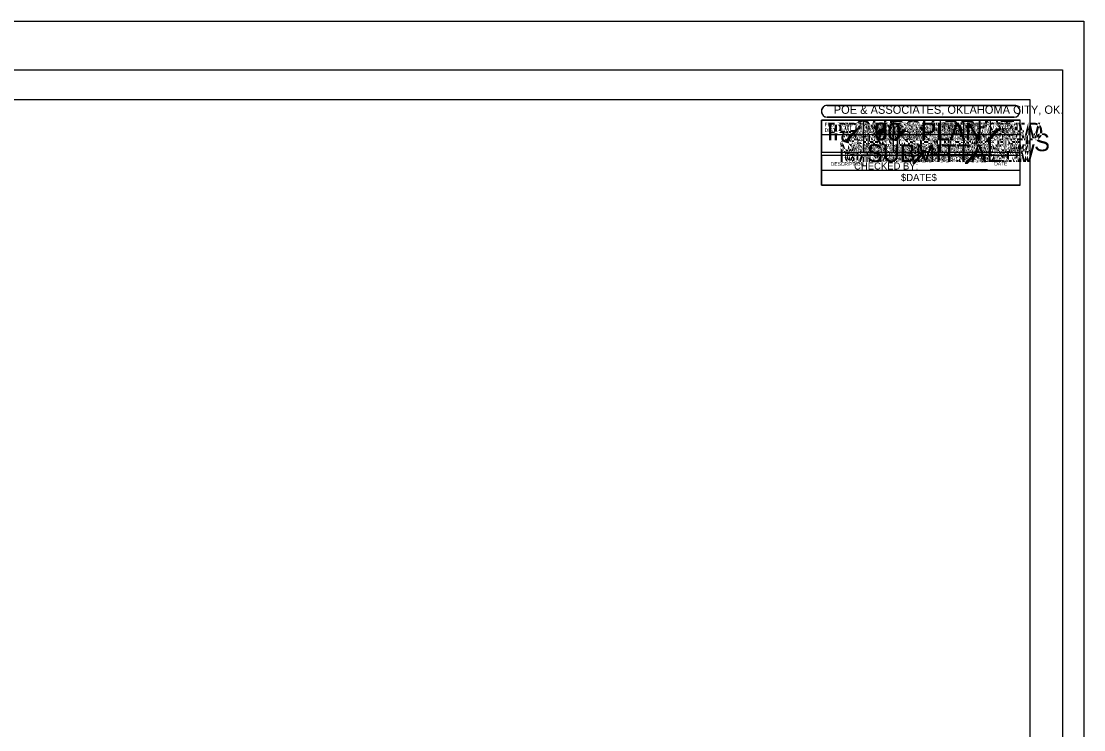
# Model space of a CAD drawing. Extents: x -434 to 1366, y -662 to 538.
# Drawn here: x 466 to 1366, y -62 to 538 of the extents above; entities that cross this region are included whole.
import ezdxf

# ---------------------------------------------------------------- set-up
doc = ezdxf.new("R2010")
doc.units = 0
for name, color, linetype in [('SHT_Date_Stamp', 7, 'Continuous'), ('SHT_Plot_Shape_Full', 7, 'Continuous'), ('SHT_Plot_Shape_Half', 7, 'Continuous'), ('SHT_Sheet_Border', 7, 'Continuous'), ('SHT_Stamp_30_Submit', 7, 'Continuous'), ('SHT_Stamp_60_Submit', 7, 'Continuous'), ('SHT_Stamp_70_Submit', 7, 'Continuous'), ('SHT_Stamp_90_Submit', 7, 'Continuous'), ('SHT_Stamp_Check_Print', 7, 'Continuous'), ('SHT_Stamp_Est_Inf', 7, 'Continuous'), ('SHT_Stamp_FFR', 7, 'Continuous'), ('SHT_Stamp_Info_Material', 7, 'Continuous'), ('SHT_Stamp_No_Const', 7, 'Continuous'), ('SHT_Stamp_No_Design', 7, 'Continuous'), ('SHT_Stamp_Plan_Hand', 7, 'Continuous'), ('SHT_Stamp_Pre_Plan', 7, 'Continuous'), ('SHT_Stamp_Prop_RW', 7, 'Continuous'), ('SHT_Stamp_Ret_Sub', 7, 'Continuous'), ('SHT_Stamp_Rev_Block', 7, 'Continuous'), ('SHT_Stamp_Rev_Prop_RW', 7, 'Continuous'), ('SHT_Stamp_Rev_Sheet', 7, 'Continuous'), ('SHT_Stamp_RW_Utilities_Meeting', 7, 'Continuous'), ('SHT_Stamp_RW_Utilities_Review', 7, 'Continuous'), ('SHT_Stamp_Send_Comments', 7, 'Continuous')]:
    doc.layers.add(name, color=color, linetype=linetype)

msp = doc.modelspace()

# ---------------------------------------------------------------- linework, layer by layer
at = {"layer": 'SHT_Plot_Shape_Full'}
msp.add_lwpolyline([(-433.98, 538.27), (1366.02, 538.27), (1366.02, -661.73), (-433.98, -661.73)], close=True, dxfattribs=at)
at = {"layer": 'SHT_Plot_Shape_Half'}
msp.add_lwpolyline([(-352.1, 497.02), (1347.9, 497.02), (1347.9, -602.98), (-352.1, -602.98)], close=True, dxfattribs=at)
at = {"layer": 'SHT_Sheet_Border'}
msp.add_lwpolyline([(1320.4, -577.98), (-254.6, -577.98), (-254.6, 472.02), (1320.4, 472.02)], close=True, dxfattribs=at)
at = {"layer": 'SHT_Stamp_30_Submit'}
for p, q in [((1148.77, 467.02), (1307.06, 467.02)), ((1143.77, 454.52), (1312.06, 454.52)), ((1143.77, 399.57), (1143.77, 454.52)), ((1148.77, 457.02), (1307.06, 457.02)), ((1312.06, 399.57), (1312.06, 454.52)), ((1205.93, 437.61), (1213.71, 446.24)), ((1206.82, 437.61), (1214.6, 446.24)), ((1207.07, 437.61), (1214.85, 446.24)), ((1207.46, 437.61), (1215.24, 446.24)), ((1213.71, 446.24), (1215.24, 446.24)), ((1205.93, 437.61), (1207.46, 437.61)), ((1143.77, 399.57), (1312.06, 399.57))]:
    msp.add_line(p, q, dxfattribs=at)
for centre, start, end in [((1148.78, 462.04), 89.99522, 270), ((1307.08, 462.04), 270, 90.00478)]:
    msp.add_arc(centre, 5, start, end, dxfattribs=at)
at = {"layer": 'SHT_Stamp_60_Submit'}
for p, q in [((1148.77, 467.02), (1307.06, 467.02)), ((1143.77, 454.52), (1312.06, 454.52)), ((1143.77, 399.57), (1143.77, 454.52)), ((1148.77, 457.02), (1307.06, 457.02)), ((1312.06, 399.57), (1312.06, 454.52)), ((1205.93, 437.61), (1213.71, 446.24)), ((1206.82, 437.61), (1214.6, 446.24)), ((1207.07, 437.61), (1214.85, 446.24)), ((1207.46, 437.61), (1215.24, 446.24)), ((1213.71, 446.24), (1215.24, 446.24)), ((1205.93, 437.61), (1207.46, 437.61)), ((1143.77, 399.57), (1312.06, 399.57))]:
    msp.add_line(p, q, dxfattribs=at)
for centre, start, end in [((1148.78, 462.04), 89.99522, 270), ((1307.08, 462.04), 270, 90.00478)]:
    msp.add_arc(centre, 5, start, end, dxfattribs=at)
at = {"layer": 'SHT_Stamp_70_Submit'}
for p, q in [((1148.77, 467.02), (1307.06, 467.02)), ((1143.77, 454.52), (1312.06, 454.52)), ((1143.77, 399.57), (1143.77, 454.52)), ((1148.77, 457.02), (1307.06, 457.02)), ((1312.06, 399.57), (1312.06, 454.52)), ((1205.93, 437.61), (1213.71, 446.24)), ((1206.82, 437.61), (1214.6, 446.24)), ((1207.07, 437.61), (1214.85, 446.24)), ((1207.46, 437.61), (1215.24, 446.24)), ((1213.71, 446.24), (1215.24, 446.24)), ((1205.93, 437.61), (1207.46, 437.61)), ((1143.77, 399.57), (1312.06, 399.57))]:
    msp.add_line(p, q, dxfattribs=at)
for centre, start, end in [((1148.78, 462.04), 89.99522, 270), ((1307.08, 462.04), 270, 90.00478)]:
    msp.add_arc(centre, 5, start, end, dxfattribs=at)
at = {"layer": 'SHT_Stamp_90_Submit'}
for p, q in [((1148.77, 467.02), (1307.06, 467.02)), ((1143.77, 454.52), (1312.06, 454.52)), ((1143.77, 399.57), (1143.77, 454.52)), ((1148.77, 457.02), (1307.06, 457.02)), ((1312.06, 399.57), (1312.06, 454.52)), ((1205.93, 437.61), (1213.71, 446.24)), ((1206.82, 437.61), (1214.6, 446.24)), ((1207.07, 437.61), (1214.85, 446.24)), ((1207.46, 437.61), (1215.24, 446.24)), ((1213.71, 446.24), (1215.24, 446.24)), ((1205.93, 437.61), (1207.46, 437.61)), ((1143.77, 399.57), (1312.06, 399.57))]:
    msp.add_line(p, q, dxfattribs=at)
for centre, start, end in [((1148.78, 462.04), 89.99522, 270), ((1307.08, 462.04), 270, 90.00478)]:
    msp.add_arc(centre, 5, start, end, dxfattribs=at)
at = {"layer": 'SHT_Stamp_Check_Print'}
for p, q in [((1148.77, 467.02), (1307.06, 467.02)), ((1143.77, 454.52), (1312.06, 454.52)), ((1143.77, 399.57), (1143.77, 454.52)), ((1148.77, 457.02), (1307.06, 457.02)), ((1312.06, 399.57), (1312.06, 454.52)), ((1235.85, 425.46), (1284.37, 425.46)), ((1235.85, 412.68), (1284.37, 412.68)), ((1143.77, 399.57), (1312.06, 399.57))]:
    msp.add_line(p, q, dxfattribs=at)
for centre, start, end in [((1148.78, 462.04), 89.99522, 270), ((1307.08, 462.04), 270, 90.00478)]:
    msp.add_arc(centre, 5, start, end, dxfattribs=at)
at = {"layer": 'SHT_Stamp_Est_Inf'}
for p, q in [((1148.77, 467.02), (1307.06, 467.02)), ((1143.77, 454.52), (1312.06, 454.52)), ((1143.77, 399.57), (1143.77, 454.52)), ((1148.77, 457.02), (1307.06, 457.02)), ((1312.06, 399.57), (1312.06, 454.52)), ((1143.77, 399.57), (1312.06, 399.57))]:
    msp.add_line(p, q, dxfattribs=at)
for centre, start, end in [((1148.78, 462.04), 89.99522, 270), ((1307.08, 462.04), 270, 90.00478)]:
    msp.add_arc(centre, 5, start, end, dxfattribs=at)
at = {"layer": 'SHT_Stamp_FFR'}
for p, q in [((1148.77, 467.02), (1307.06, 467.02)), ((1143.77, 454.52), (1312.06, 454.52)), ((1143.77, 399.57), (1143.77, 454.52)), ((1148.77, 457.02), (1307.06, 457.02)), ((1312.06, 399.57), (1312.06, 454.52)), ((1143.77, 399.57), (1312.06, 399.57))]:
    msp.add_line(p, q, dxfattribs=at)
for centre, start, end in [((1148.78, 462.04), 89.99522, 270), ((1307.08, 462.04), 270, 90.00478)]:
    msp.add_arc(centre, 5, start, end, dxfattribs=at)
at = {"layer": 'SHT_Stamp_Info_Material'}
for p, q in [((1148.77, 467.02), (1307.06, 467.02)), ((1143.77, 454.52), (1312.06, 454.52)), ((1143.77, 399.57), (1143.77, 454.52)), ((1148.77, 457.02), (1307.06, 457.02)), ((1312.06, 399.57), (1312.06, 454.52)), ((1143.77, 399.57), (1312.06, 399.57))]:
    msp.add_line(p, q, dxfattribs=at)
for centre, start, end in [((1148.78, 462.04), 89.99522, 270), ((1307.08, 462.04), 270, 90.00478)]:
    msp.add_arc(centre, 5, start, end, dxfattribs=at)
at = {"layer": 'SHT_Stamp_No_Const'}
for p, q in [((1148.77, 467.02), (1307.06, 467.02)), ((1143.77, 454.52), (1312.06, 454.52)), ((1143.77, 399.57), (1143.77, 454.52)), ((1148.77, 457.02), (1307.06, 457.02)), ((1312.06, 399.57), (1312.06, 454.52)), ((1143.77, 399.57), (1312.06, 399.57))]:
    msp.add_line(p, q, dxfattribs=at)
for centre, start, end in [((1148.78, 462.04), 89.99522, 270), ((1307.08, 462.04), 270, 90.00478)]:
    msp.add_arc(centre, 5, start, end, dxfattribs=at)
at = {"layer": 'SHT_Stamp_No_Design'}
for p, q in [((1148.77, 467.02), (1307.06, 467.02)), ((1143.77, 454.52), (1312.06, 454.52)), ((1143.77, 399.57), (1143.77, 454.52)), ((1148.77, 457.02), (1307.06, 457.02)), ((1312.06, 399.57), (1312.06, 454.52)), ((1143.77, 399.57), (1312.06, 399.57))]:
    msp.add_line(p, q, dxfattribs=at)
for centre, start, end in [((1148.78, 462.04), 89.99522, 270), ((1307.08, 462.04), 270, 90.00478)]:
    msp.add_arc(centre, 5, start, end, dxfattribs=at)
at = {"layer": 'SHT_Stamp_Plan_Hand'}
for p, q in [((1148.77, 467.02), (1307.06, 467.02)), ((1143.77, 454.52), (1312.06, 454.52)), ((1143.77, 399.57), (1143.77, 454.52)), ((1148.77, 457.02), (1307.06, 457.02)), ((1312.06, 399.57), (1312.06, 454.52)), ((1143.77, 399.57), (1312.06, 399.57))]:
    msp.add_line(p, q, dxfattribs=at)
for centre, start, end in [((1148.78, 462.04), 89.99522, 270), ((1307.08, 462.04), 270, 90.00478)]:
    msp.add_arc(centre, 5, start, end, dxfattribs=at)
at = {"layer": 'SHT_Stamp_Pre_Plan'}
for p, q in [((1148.77, 467.02), (1307.06, 467.02)), ((1143.77, 454.52), (1312.06, 454.52)), ((1143.77, 399.57), (1143.77, 454.52)), ((1148.77, 457.02), (1307.06, 457.02)), ((1312.06, 399.57), (1312.06, 454.52)), ((1143.77, 399.57), (1312.06, 399.57))]:
    msp.add_line(p, q, dxfattribs=at)
for centre, start, end in [((1148.78, 462.04), 89.99522, 270), ((1307.08, 462.04), 270, 90.00478)]:
    msp.add_arc(centre, 5, start, end, dxfattribs=at)
at = {"layer": 'SHT_Stamp_Prop_RW'}
for p, q in [((1148.77, 467.02), (1307.06, 467.02)), ((1143.77, 454.52), (1312.06, 454.52)), ((1143.77, 399.57), (1143.77, 454.52)), ((1148.77, 457.02), (1307.06, 457.02)), ((1312.06, 399.57), (1312.06, 454.52)), ((1221.11, 418.15), (1230.71, 428.81)), ((1222.21, 418.15), (1231.81, 428.81)), ((1222.52, 418.15), (1232.12, 428.81)), ((1223, 418.15), (1232.6, 428.81)), ((1230.71, 428.81), (1232.6, 428.81)), ((1221.11, 418.15), (1223, 418.15)), ((1143.77, 399.57), (1312.06, 399.57))]:
    msp.add_line(p, q, dxfattribs=at)
for centre, start, end in [((1148.78, 462.04), 89.99522, 270), ((1307.08, 462.04), 270, 90.00478)]:
    msp.add_arc(centre, 5, start, end, dxfattribs=at)
at = {"layer": 'SHT_Stamp_Ret_Sub'}
for p, q in [((1148.77, 467.02), (1307.06, 467.02)), ((1143.77, 454.52), (1312.06, 454.52)), ((1143.77, 399.57), (1143.77, 454.52)), ((1148.77, 457.02), (1307.06, 457.02)), ((1312.06, 399.57), (1312.06, 454.52)), ((1143.77, 399.57), (1312.06, 399.57))]:
    msp.add_line(p, q, dxfattribs=at)
for centre, start, end in [((1148.78, 462.04), 89.99522, 270), ((1307.08, 462.04), 270, 90.00478)]:
    msp.add_arc(centre, 5, start, end, dxfattribs=at)
at = {"layer": 'SHT_Stamp_Rev_Block'}
for p, q in [((1307.06, 467.02), (1148.78, 467.02)), ((1312.06, 454.52), (1143.77, 454.52)), ((1143.77, 454.52), (1143.77, 427.02)), ((1307.06, 457.02), (1148.78, 457.02)), ((1179.56, 454.52), (1179.56, 427.02)), ((1204.56, 454.52), (1204.56, 427.02)), ((1244.56, 427.02), (1244.56, 454.52)), ((1264.56, 427.02), (1264.56, 454.52)), ((1287.06, 427.02), (1287.06, 454.52)), ((1312.06, 427.02), (1312.06, 454.52)), ((1312.06, 442.02), (1143.77, 442.02)), ((1312.06, 427.02), (1143.77, 427.02)), ((1312.06, 424.52), (1143.77, 424.52)), ((1143.77, 424.52), (1143.77, 399.52)), ((1312.06, 399.52), (1312.06, 424.52)), ((1312.06, 412.02), (1143.77, 412.02)), ((1312.06, 399.52), (1143.77, 399.52))]:
    msp.add_line(p, q, dxfattribs=at)
for centre, start, end in [((1148.78, 462), 90, 270), ((1307.06, 462.02), 270, 90)]:
    msp.add_arc(centre, 5, start, end, dxfattribs=at)
at = {"layer": 'SHT_Stamp_Rev_Prop_RW'}
for p, q in [((1148.77, 467.02), (1307.06, 467.02)), ((1143.77, 454.52), (1312.06, 454.52)), ((1143.77, 399.57), (1143.77, 454.52)), ((1148.77, 457.02), (1307.06, 457.02)), ((1312.06, 399.57), (1312.06, 454.52)), ((1265.62, 418.01), (1275.22, 428.67)), ((1266.72, 418.01), (1276.32, 428.67)), ((1267.03, 418.01), (1276.63, 428.67)), ((1267.51, 418.01), (1277.11, 428.67)), ((1275.22, 428.67), (1277.11, 428.67)), ((1265.62, 418.01), (1267.51, 418.01)), ((1143.77, 399.57), (1312.06, 399.57))]:
    msp.add_line(p, q, dxfattribs=at)
for centre, start, end in [((1148.78, 462.04), 89.99522, 270), ((1307.08, 462.04), 270, 90.00478)]:
    msp.add_arc(centre, 5, start, end, dxfattribs=at)
at = {"layer": 'SHT_Stamp_Rev_Sheet'}
for p, q in [((1148.77, 467.02), (1307.06, 467.02)), ((1143.77, 454.52), (1312.06, 454.52)), ((1143.77, 399.57), (1143.77, 454.52)), ((1148.77, 457.02), (1307.06, 457.02)), ((1312.06, 399.57), (1312.06, 454.52)), ((1143.77, 399.57), (1312.06, 399.57))]:
    msp.add_line(p, q, dxfattribs=at)
for centre, start, end in [((1148.78, 462.04), 89.99522, 270), ((1307.08, 462.04), 270, 90.00478)]:
    msp.add_arc(centre, 5, start, end, dxfattribs=at)
at = {"layer": 'SHT_Stamp_RW_Utilities_Meeting'}
for p, q in [((1148.77, 467.02), (1307.06, 467.02)), ((1143.77, 454.52), (1312.06, 454.52)), ((1143.77, 399.57), (1143.77, 454.52)), ((1148.77, 457.02), (1307.06, 457.02)), ((1312.06, 399.57), (1312.06, 454.52)), ((1163.87, 436.5), (1173.47, 447.15)), ((1164.97, 436.5), (1174.57, 447.15)), ((1165.28, 436.5), (1174.88, 447.15)), ((1165.76, 436.5), (1175.36, 447.15)), ((1173.47, 447.15), (1175.36, 447.15)), ((1163.87, 436.5), (1165.76, 436.5)), ((1143.77, 399.57), (1312.06, 399.57))]:
    msp.add_line(p, q, dxfattribs=at)
for centre, start, end in [((1148.78, 462.04), 89.99522, 270), ((1307.08, 462.04), 270, 90.00478)]:
    msp.add_arc(centre, 5, start, end, dxfattribs=at)
at = {"layer": 'SHT_Stamp_RW_Utilities_Review'}
for p, q in [((1148.77, 467.02), (1307.06, 467.02)), ((1143.77, 454.52), (1312.06, 454.52)), ((1143.77, 399.57), (1143.77, 454.52)), ((1148.77, 457.02), (1307.06, 457.02)), ((1312.06, 399.57), (1312.06, 454.52)), ((1283.31, 436.5), (1292.91, 447.15)), ((1284.41, 436.5), (1294.01, 447.15)), ((1284.72, 436.5), (1294.32, 447.15)), ((1285.2, 436.5), (1294.8, 447.15)), ((1292.91, 447.15), (1294.8, 447.15)), ((1283.31, 436.5), (1285.2, 436.5)), ((1143.77, 399.57), (1312.06, 399.57))]:
    msp.add_line(p, q, dxfattribs=at)
for centre, start, end in [((1148.78, 462.04), 89.99522, 270), ((1307.08, 462.04), 270, 90.00478)]:
    msp.add_arc(centre, 5, start, end, dxfattribs=at)
at = {"layer": 'SHT_Stamp_Send_Comments'}
for p, q in [((1148.77, 467.02), (1307.06, 467.02)), ((1143.77, 454.52), (1312.06, 454.52)), ((1143.77, 399.57), (1143.77, 454.52)), ((1148.77, 457.02), (1307.06, 457.02)), ((1312.06, 399.57), (1312.06, 454.52)), ((1143.77, 399.57), (1312.06, 399.57))]:
    msp.add_line(p, q, dxfattribs=at)
for centre, start, end in [((1148.78, 462.04), 89.99522, 270), ((1307.08, 462.04), 270, 90.00478)]:
    msp.add_arc(centre, 5, start, end, dxfattribs=at)

# ---------------------------------------------------------------- texts
at = {"layer": 'SHT_Date_Stamp'}
msp.add_text('$DATE$', height=6, dxfattribs=at).set_placement((1211.21, 402.98))
at = {"layer": 'SHT_Stamp_30_Submit'}
for s, height, p in [('POE & ASSOCIATES, OKLAHOMA CITY, OK.', 7, (1154.27, 459.89)), ('30   PLAN', 15, (1188.88, 437.42)), ('O', 7.65, (1204.21, 441.86)), ('O', 7.65, (1211.81, 437.64)), ('SUBMITTAL', 15, (1182.33, 419.09))]:
    msp.add_text(s, height=height, dxfattribs=at).set_placement(p)
at = {"layer": 'SHT_Stamp_60_Submit'}
for s, height, p in [('POE & ASSOCIATES, OKLAHOMA CITY, OK.', 7, (1154.27, 459.89)), ('60   PLAN', 15, (1188.53, 437.42)), ('O', 7.65, (1204.21, 441.86)), ('O', 7.65, (1211.81, 437.64)), ('SUBMITTAL', 15, (1182.33, 419.09))]:
    msp.add_text(s, height=height, dxfattribs=at).set_placement(p)
at = {"layer": 'SHT_Stamp_70_Submit'}
for s, height, p in [('POE & ASSOCIATES, OKLAHOMA CITY, OK.', 7, (1154.27, 459.89)), ('70   PLAN', 15, (1188.53, 437.42)), ('O', 7.65, (1204.21, 441.86)), ('O', 7.65, (1211.81, 437.64)), ('SUBMITTAL', 15, (1182.33, 419.09))]:
    msp.add_text(s, height=height, dxfattribs=at).set_placement(p)
at = {"layer": 'SHT_Stamp_90_Submit'}
for s, height, p in [('POE & ASSOCIATES, OKLAHOMA CITY, OK.', 7, (1154.27, 459.89)), ('90   PLAN', 15, (1188.53, 437.42)), ('O', 7.65, (1204.21, 441.86)), ('O', 7.65, (1211.81, 437.64)), ('SUBMITTAL', 15, (1182.33, 419.09))]:
    msp.add_text(s, height=height, dxfattribs=at).set_placement(p)
at = {"layer": 'SHT_Stamp_Check_Print'}
for s, height, p in [('POE & ASSOCIATES, OKLAHOMA CITY, OK.', 7, (1154.28, 459.91)), ('CHECK PRINT', 15, (1171.4, 439.6)), ('REVISED BY:', 6, (1171.46, 425.44)), ('CHECKED BY:', 6, (1171.46, 412.69))]:
    msp.add_text(s, height=height, dxfattribs=at).set_placement(p)
at = {"layer": 'SHT_Stamp_Est_Inf'}
for s, height, p in [('POE & ASSOCIATES, OKLAHOMA CITY, OK.', 7, (1154.28, 459.91)), ('BASED ON EST.', 15, (1165.32, 437.42)), ('INFORMATION', 15, (1171.4, 419.09))]:
    msp.add_text(s, height=height, dxfattribs=at).set_placement(p)
at = {"layer": 'SHT_Stamp_FFR'}
for s, height, p in [('POE & ASSOCIATES, OKLAHOMA CITY, OK.', 7, (1154.28, 459.91)), ('FINAL FIELD', 15, (1176.36, 437.42)), ('REVIEW', 15, (1197.74, 419.09))]:
    msp.add_text(s, height=height, dxfattribs=at).set_placement(p)
at = {"layer": 'SHT_Stamp_Info_Material'}
for s, height, p in [('POE & ASSOCIATES, OKLAHOMA CITY, OK.', 7, (1154.28, 459.91)), ('INFORMATION', 15, (1171.4, 437.42)), ('MATERIAL ONLY', 15, (1158.47, 419.09))]:
    msp.add_text(s, height=height, dxfattribs=at).set_placement(p)
at = {"layer": 'SHT_Stamp_No_Const'}
for s, height, p in [('POE & ASSOCIATES, OKLAHOMA CITY, OK.', 7, (1154.28, 459.91)), ('NOT TO BE USED', 15, (1155.81, 437.42)), ('FOR CONST.', 15, (1180.32, 419.09))]:
    msp.add_text(s, height=height, dxfattribs=at).set_placement(p)
at = {"layer": 'SHT_Stamp_No_Design'}
for s, height, p in [('POE & ASSOCIATES, OKLAHOMA CITY, OK.', 7, (1154.28, 459.91)), ('NOT TO BE USED', 15, (1155.81, 437.42)), ('FOR DESIGN', 15, (1179.43, 419.09))]:
    msp.add_text(s, height=height, dxfattribs=at).set_placement(p)
at = {"layer": 'SHT_Stamp_Plan_Hand'}
for s, height, p in [('POE & ASSOCIATES, OKLAHOMA CITY, OK.', 7, (1154.28, 459.91)), ('PLAN-IN-HAND', 15, (1167.98, 428.26))]:
    msp.add_text(s, height=height, dxfattribs=at).set_placement(p)
at = {"layer": 'SHT_Stamp_Pre_Plan'}
for s, height, p in [('POE & ASSOCIATES, OKLAHOMA CITY, OK.', 7, (1154.28, 459.91)), ('PRELIMINARY', 15, (1172.17, 437.42)), ('PLANS', 15, (1202.53, 419.09))]:
    msp.add_text(s, height=height, dxfattribs=at).set_placement(p)
at = {"layer": 'SHT_Stamp_Prop_RW'}
for s, height, p in [('POE & ASSOCIATES, OKLAHOMA CITY, OK.', 7, (1154.28, 459.91)), ('PROPOSED', 15, (1189.24, 437.42)), ('R W', 15, (1210.85, 419.09))]:
    msp.add_text(s, height=height, dxfattribs=at).set_placement(p)
at = {"layer": 'SHT_Stamp_Ret_Sub'}
for s, height, p in [('POE & ASSOCIATES, OKLAHOMA CITY, OK.', 7, (1154.28, 459.91)), ('RET. SUBMITTED', 15, (1164.67, 437.42)), ('MATERIALS', 15, (1181.74, 419.09))]:
    msp.add_text(s, height=height, dxfattribs=at).set_placement(p)
at = {"layer": 'SHT_Stamp_Rev_Block'}
for s, height, p in [('POE & ASSOCIATES, OKLAHOMA CITY, OK.', 7, (1154.28, 459.91)), ('FED.  ROAD', 3, (1146.56, 449.27)), ('FISCAL', 3, (1246.21, 449.27)), ('SHEET', 3, (1268.96, 449.27)), ('TOTAL', 3, (1292.68, 449.27)), ('DIST.  NO.', 3, (1146.57, 444.48)), ('STATE', 3, (1185.18, 446.77)), ('JOB PIECE NO.', 3, (1206.15, 446.77)), ('YEAR', 3, (1249.16, 444.48)), ('NO.', 3, (1271.88, 444.27)), ('SHEETS', 3, (1291.13, 444.48)), ('6', 4, (1159.53, 432.52)), ('OKLA.', 4, (1182.89, 432.52)), ('DESCRIPTION', 3, (1151.76, 415.94)), ('REVISIONS', 3, (1214.18, 418.9)), ('DATE', 3, (1290.24, 416.15))]:
    msp.add_text(s, height=height, dxfattribs=at).set_placement(p)
at = {"layer": 'SHT_Stamp_Rev_Prop_RW'}
for s, height, p in [('POE & ASSOCIATES, OKLAHOMA CITY, OK.', 7, (1154.28, 459.91)), ('REVISED', 15, (1195.62, 437.42)), ('PROPOSED R W', 15, (1166.32, 419.09))]:
    msp.add_text(s, height=height, dxfattribs=at).set_placement(p)
at = {"layer": 'SHT_Stamp_Rev_Sheet'}
for s, height, p in [('POE & ASSOCIATES, OKLAHOMA CITY, OK.', 7, (1154.28, 459.91)), ('REVISED SHEET', 15, (1165.5, 428.26))]:
    msp.add_text(s, height=height, dxfattribs=at).set_placement(p)
at = {"layer": 'SHT_Stamp_RW_Utilities_Meeting'}
for s, height, p in [('POE & ASSOCIATES, OKLAHOMA CITY, OK.', 7, (1154.27, 459.89)), ('R W & UTILITIES', 15, (1153.51, 437.42)), ('MEETING', 15, (1191.95, 419.09))]:
    msp.add_text(s, height=height, dxfattribs=at).set_placement(p)
at = {"layer": 'SHT_Stamp_RW_Utilities_Review'}
for s, height, p in [('POE & ASSOCIATES, OKLAHOMA CITY, OK.', 7, (1154.27, 459.89)), ('PRELIMINARY R W', 15, (1148.73, 437.42)), ('& UTIL.  REVIEW', 15, (1162.9, 419.09))]:
    msp.add_text(s, height=height, dxfattribs=at).set_placement(p)
at = {"layer": 'SHT_Stamp_Send_Comments'}
for s, height, p in [('POE & ASSOCIATES, OKLAHOMA CITY, OK.', 7, (1154.28, 459.91)), ('SEND COMMENTS', 15, (1159.06, 428.26))]:
    msp.add_text(s, height=height, dxfattribs=at).set_placement(p)

doc.saveas('drawing.dxf')
